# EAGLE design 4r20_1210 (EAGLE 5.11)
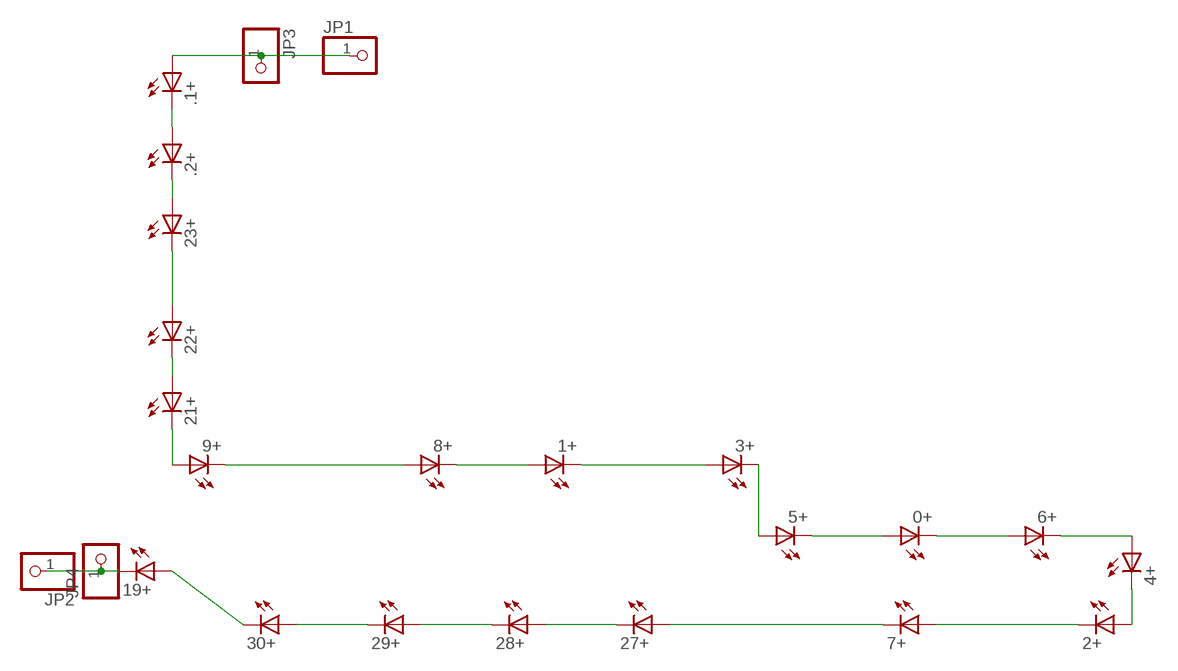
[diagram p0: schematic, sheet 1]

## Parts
0+  LED1210  [1210]
1+  LED1210  [1210]
2+  LED1210  [1210]
3+  LED1210  [1210]
4+  LED1210  [1210]
5+  LED1210  [1210]
6+  LED1210  [1210]
7+  LED1210  [1210]
8+  LED1210  [1210]
9+  LED1210  [1210]
19+  LED1210  [1210]
21+  LED1210  [1210]
22+  LED1210  [1210]
23+  LED1210  [1210]
27+  LED1210  [1210]
28+  LED1210  [1210]
29+  LED1210  [1210]
30+  LED1210  [1210]
.1+  LED1210  [1210]
.2+  LED1210  [1210]
JP1  PINHD-1X11X0.4  [1X01]
JP2  PINHD-1X11X0.4  [1X01]
JP3  PINHD-1X11MM6  [1X1MM8]
JP4  PINHD-1X11MM6  [1X1MM8]

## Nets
MINUS: 19+.P$2(C) JP2.1 JP4.1
N$4: 19+.P$1(A) 30+.P$2(C)
N$6: 8+.P$1(A) 9+.P$2(C)
N$7: 29+.P$2(C) 30+.P$1(A)
N$8: 28+.P$2(C) 29+.P$1(A)
N$9: 27+.P$2(C) 28+.P$1(A)
N$12: 2+.P$2(C) 7+.P$1(A)
N$13: 7+.P$2(C) 27+.P$1(A)
N$14: 2+.P$1(A) 4+.P$2(C)
N$15: 4+.P$1(A) 6+.P$2(C)
N$16: 0+.P$2(C) 6+.P$1(A)
N$17: 0+.P$1(A) 5+.P$2(C)
N$18: 3+.P$2(C) 5+.P$1(A)
N$19: 1+.P$2(C) 3+.P$1(A)
N$20: 1+.P$1(A) 8+.P$2(C)
N$23: 9+.P$1(A) 21+.P$2(C)
N$24: 21+.P$1(A) 22+.P$2(C)
N$25: 22+.P$1(A) 23+.P$2(C)
N$26: .1+.P$2(C) .2+.P$1(A)
N$28: 23+.P$1(A) .2+.P$2(C)
PLUS: .1+.P$1(A) JP1.1 JP3.1

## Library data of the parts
0+ 1+ 2+ 3+ 4+ 5+ 6+ 7+ 8+ 9+ 19+ 21+ 22+ 23+ 27+ 28+ 29+ 30+ .1+ .2+ = led(2):LED: LED
JP1-JP4 = pinhead:PINHD-1X1: PIN HEADER

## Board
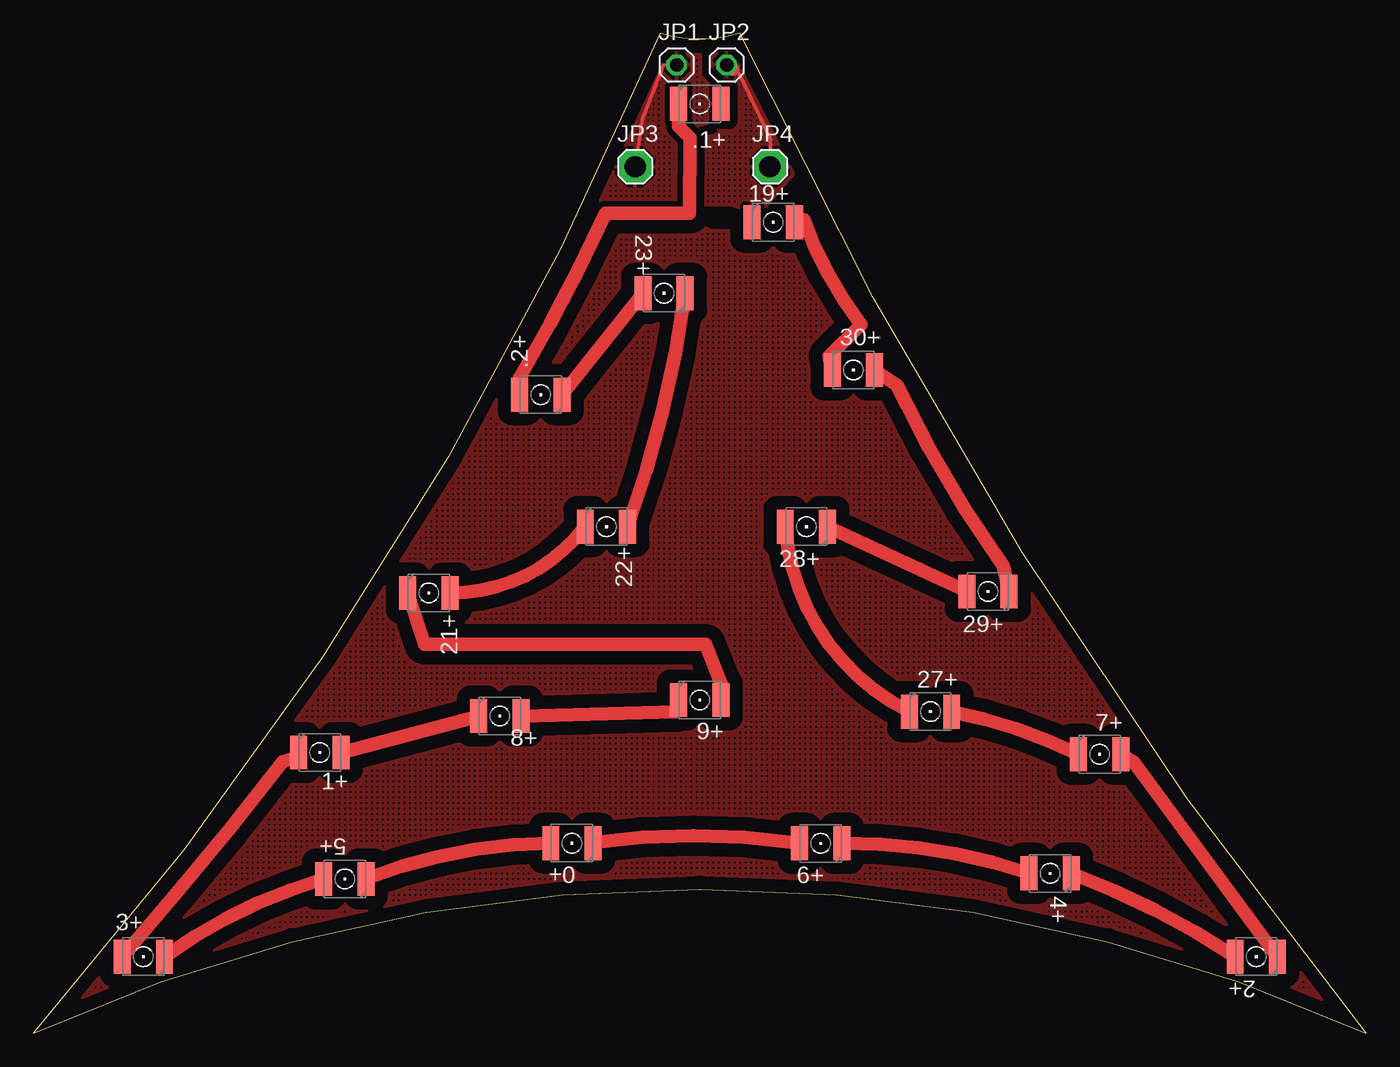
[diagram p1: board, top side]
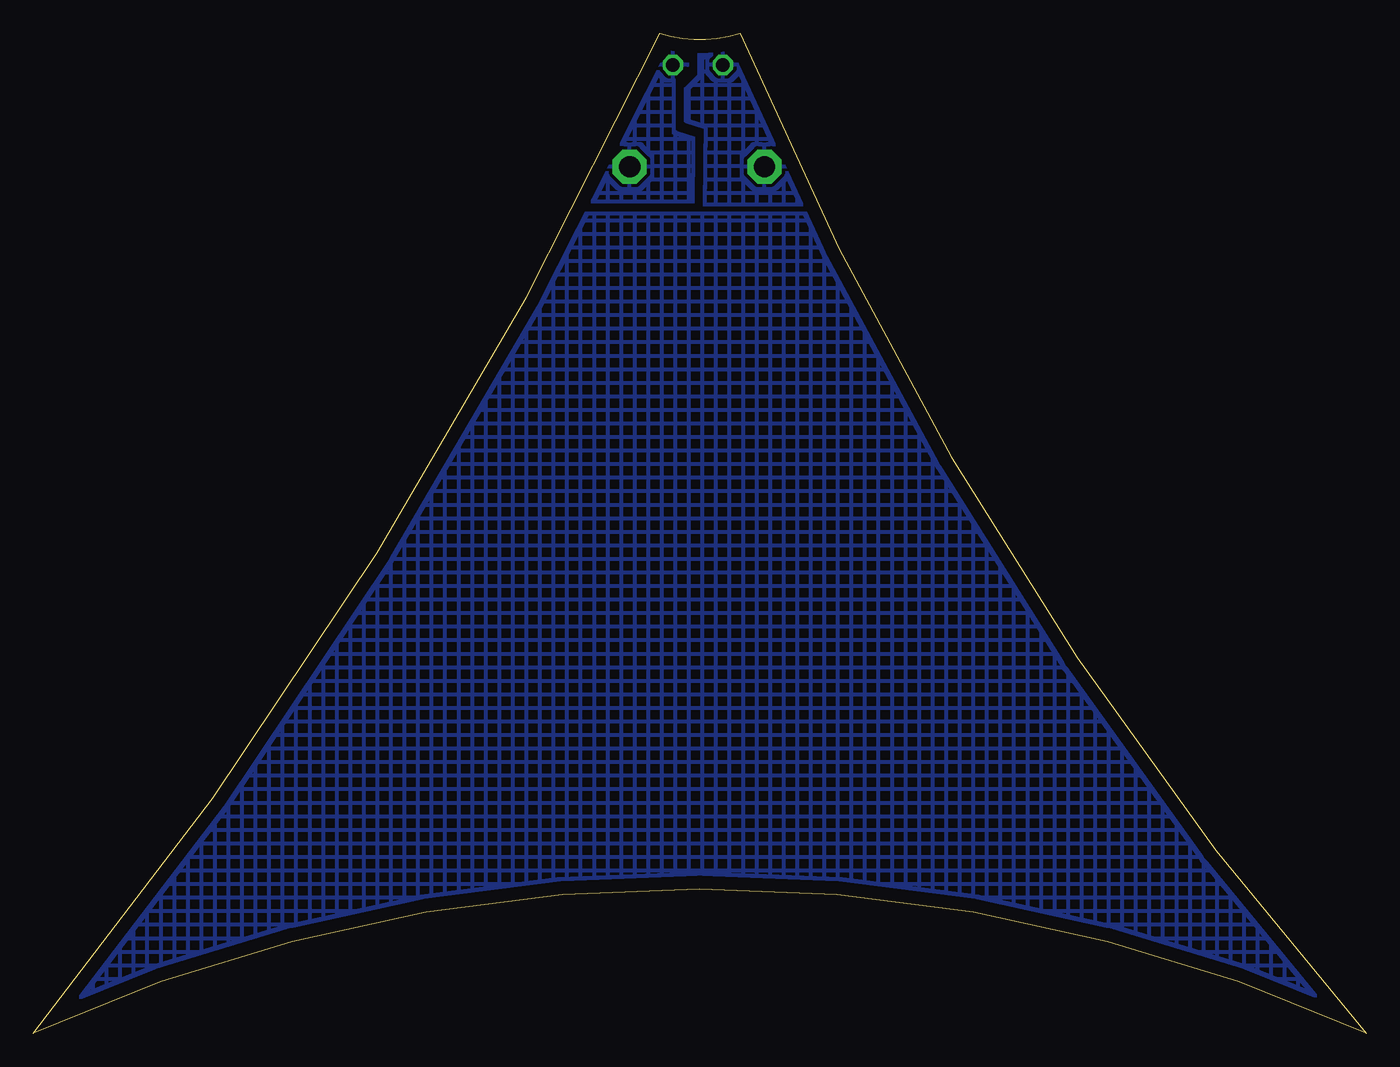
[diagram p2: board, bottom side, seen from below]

Size 100 x 75 mm. Coordinates in mm from the lower left corner, seen from the top.
Outline: 0,0 arc-49 100,0 arc-14 53,75 arc-36 47,75 arc-18 0,0
Copper layers (1*16): Top 0.035mm / dielectric 1.5mm / Bottom 0.035mm
Design rules "default": minimum track width 10mil, minimum drill 24mil, track to track 8mil, track to pad 8mil, pad to pad 8mil, via to via 8mil, smd to smd 8mil, copper to edge 40mil, drill to drill 8mil, minimum pad ring 10mil, minimum via ring 8mil, stop-mask expansion 4mil, vias tented up to drill 0mil, thermal gap 10mil

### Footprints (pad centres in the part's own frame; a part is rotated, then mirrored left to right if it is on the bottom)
1210 = smd 1.27 x 2.54: P$1 1.587,0; P$2 -1.587,0
1X01 = drill 1.016 octagon: 1 0,0
1X1MM8 = drill 1.6 pad 2.54 octagon: 1 0,0

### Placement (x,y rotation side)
0+  40.41,14.26 180 top
1+  21.49,21.06 0 top
2+  91.75,5.75 180 top
3+  8.25,5.75 180 top
4+  76.29,12 180 top
5+  23.38,11.58 180 top
6+  59.07,14.25 180 top
7+  80,20.93 0 top
8+  35,23.8 0 top
9+  50,25 0 top
19+  55.51,60.83 0 top
21+  29.68,33.03 0 top
22+  43,38 0 top
23+  47.32,55.51 180 top
27+  67.31,24.13 0 top
28+  58,38 180 top
29+  71.62,33.14 180 top
30+  61.53,49.75 0 top
.1+  50,69.71 0 top
.2+  38.07,47.9 180 top
JP1  48.26,72.63 0 top
JP2  52.01,72.63 0 top
JP3  45.15,65 0 top
JP4  55.26,65 0 top

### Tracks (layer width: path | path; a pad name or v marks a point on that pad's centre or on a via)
MINUS
  Top 0.254: 52.49,72.32 52.95,71.99 55.31,67.09 JP4.1
  Top 1.016: 52.49,72.32 JP2.1
  pour Top (isolate 0.61, rank 3, hatched): 53.23,73.58 57.32,64.78 54.46,61.44 52.36,62.15 49.24,62.11 50.46,73.56
  pour Bottom (isolate 0.61, rank 3, hatched): 53.23,73.58 59.19,61.7 49.82,61.7 50.46,73.56
N$1
  pour Top (isolate 1.016, hatched): 41.08,60.96 27.71,37.07 arc-19 -0.71,-0.23 arc-46 100,0 arc-14 60.32,60.57 58.42,60.2 50.8,60.2 49.53,60.96
  pour Bottom (isolate 1.016, hatched): 27.71,37.07 arc-19 -0.71,-0.23 arc-46 100,0 arc-14 60.32,61.5 40.64,61.5
N$4
  Top 1.016: 19+.P$1 57.28,60.83 57.82,61.01 arc18 62.11,53.16 59.69,50.8 30+.P$2
N$6
  Top 1.016: 8+.P$1 48.26,24.13 9+.P$2
N$7
  Top 1.016: 29+.P$2 72.77,35.04 arc-10 64.79,48.61 30+.P$1
N$8
  Top 1.016: 28+.P$2 29+.P$1
N$9
  Top 0.254: 27+.P$2 66.04,24.13
  Top 1.016: 27+.P$2 arc-59 28+.P$1
N$12
  Top 1.016: 2+.P$2 82.55,20.32 7+.P$1
N$13
  Top 0.254: 27+.P$1 68.58,24.13
  Top 1.016: 27+.P$1 arc-14 7+.P$2
N$14
  Top 1.016: 4+.P$2 arc-13 2+.P$1
N$15
  Top 1.016: 6+.P$2 arc-20 4+.P$1
N$16
  Top 0.254: 0+.P$2 41.91,14.31 | 57.15,14.31 6+.P$1
  Top 1.016: 41.91,14.31 arc-16 57.15,14.31
N$17
  Top 1.016: 5+.P$2 arc-21 0+.P$1
N$18
  Top 1.016: 3+.P$2 arc-20 5+.P$1
N$19
  Top 1.016: 1+.P$2 19.48,20.65 18.71,20.37 arc-3 3+.P$1
N$20
  Top 1.016: 1+.P$1 8+.P$2
N$23
  Top 1.016: 21+.P$2 29.35,29.2 50.43,29.2 51.66,26.08 9+.P$1
N$24
  Top 1.016: 21+.P$1 arc52 22+.P$2
N$25
  Top 0.254: 22+.P$1 44.45,36.83
  Top 1.016: 22+.P$1 arc12 23+.P$2
N$26
  Top 0.254: .2+.P$1 36.48,49.16
  Top 1.016: 36.48,49.16 arc6 42.93,61.5 49.23,61.5 49.26,67.18 48.41,68.03 .1+.P$2
N$28
  Top 1.016: .2+.P$2 23+.P$1
PLUS
  Top 0.254: JP3.1 45.72,68.58 47.28,72.61 JP1.1
  pour Top (isolate 0.406, rank 2, hatched): 47.04,73.98 50.05,73.65 50.05,71.83 51.07,70.81 51.07,68.47 51.01,68.41 49.57,67.97 49.59,65.54 49.65,61.73 42.15,61.64
  pour Bottom (isolate 0.406, rank 2, hatched): 47.04,73.98 50.05,73.65 50.05,71.83 51.07,70.81 51.07,68.47 51.01,68.41 49.57,67.97 49.59,65.54 49.65,61.7 42.15,61.7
